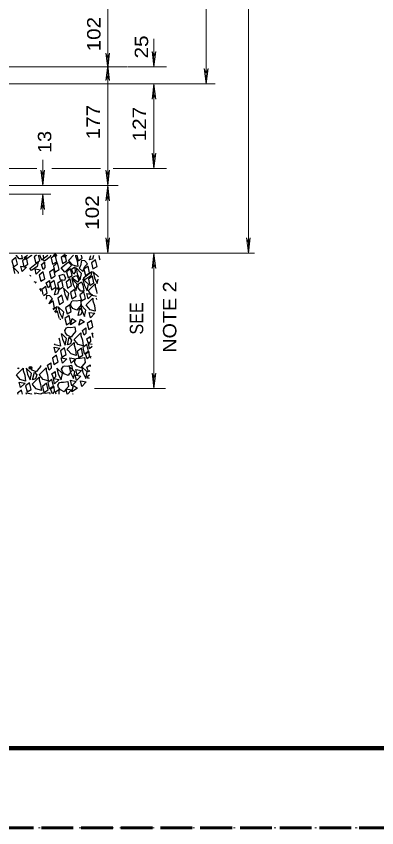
# Model space of a CAD drawing. Extents: x 312583 to 312854, y 144419 to 144597.
# Drawn here: x 312670.78 to 312691.2, y 144418.58 to 144464.5 of the extents above; entities that cross this region are included whole.
import ezdxf

# ---------------------------------------------------------------- set-up
doc = ezdxf.new("R2010")
doc.units = 0
doc.header["$LTSCALE"] = 0.3
doc.header["$PDMODE"] = 32
doc.header["$PDSIZE"] = 0.15
doc.linetypes.add('DOTTED', pattern=[1.5, 0.3, -1.2])
doc.linetypes.add('LONG_DASHED', pattern=[7.5, 6, -1.5])
for name, color, linetype, lineweight in [('1', 7, 'Continuous', 25), ('2', 7, 'Continuous', 13), ('63', 7, 'DOTTED', 13)]:
    doc.layers.add(name, color=color, linetype=linetype, lineweight=lineweight)

msp = doc.modelspace()

# ---------------------------------------------------------------- linework, layer by layer
at = {"layer": '1'}
for p, q in [((312671.6438, 144450.9791), (312671.6361, 144450.9561)), ((312672.1191, 144450.6801), (312672.0425, 144450.9791)), ((312672.7248, 144450.9791), (312672.6941, 144450.8871)), ((312672.9931, 144450.9714), (312672.9855, 144450.9714)), ((312674.1355, 144450.9714), (312674.1355, 144450.9254)), ((312674.5111, 144450.8104), (312674.4728, 144450.9714)), ((312670.9001, 144449.9518), (312670.9078, 144449.9978)), ((312671.5441, 144449.8291), (312671.5748, 144449.8521)), ((312671.5748, 144449.8521), (312671.5825, 144449.7831)), ((312671.7818, 144449.4841), (312671.9121, 144449.4611)), ((312671.9121, 144449.4611), (312671.8431, 144449.3921)), ((312672.1575, 144448.9551), (312672.1575, 144448.9398)), ((312672.3185, 144448.7021), (312672.5331, 144448.8324)), ((312675.1245, 144448.4031), (312675.2088, 144448.1348)), ((312672.8475, 144447.9354), (312672.9548, 144448.0044)), ((312673.0161, 144447.8358), (312672.9471, 144447.7821)), ((312673.1925, 144447.4294), (312673.2078, 144447.4371)), ((312673.6218, 144446.2641), (312673.3381, 144446.5478)), ((312674.9635, 144444.7844), (312674.9635, 144444.6848)), ((312673.1925, 144443.3814), (312673.2001, 144443.1208)), ((312673.9131, 144443.3584), (312673.6755, 144443.1208)), ((312671.6668, 144443.1361), (312671.6438, 144443.1208)), ((312672.1575, 144443.1361), (312672.1421, 144443.1208)), ((312673.9591, 144443.1208), (312673.9898, 144443.1361)), ((312673.9898, 144443.1361), (312673.9898, 144443.1208))]:
    msp.add_line(p, q, dxfattribs=at)
at = {"layer": '1', "lineweight": 158}
msp.add_line((312616.5, 144423.0846), (312849, 144423.0846), dxfattribs=at)
at = {"layer": '1', "linetype": 'LONG_DASHED', "lineweight": 60}
msp.add_line((312851.75, 144418.5846), (312583.526, 144418.5846), dxfattribs=at)
at = {"layer": '1'}
for points in [[(312670.8465, 144450.4654), (312670.7621, 144450.8411), (312670.5321, 144450.6648), (312670.6165, 144450.3198)], [(312671.4445, 144450.4654), (312671.3601, 144450.8411), (312671.1301, 144450.6648), (312671.2145, 144450.3198)], [(312671.9581, 144450.3428), (312671.6361, 144450.1128), (312671.5518, 144450.2278), (312672.0271, 144450.5958)], [(312672.3875, 144450.5804), (312672.4028, 144450.2738), (312672.3031, 144450.1741), (312672.2035, 144450.4501)], [(312673.0698, 144450.6111), (312672.9778, 144450.9944), (312672.7478, 144450.8181), (312672.8321, 144450.4654)], [(312673.6295, 144450.6494), (312673.5451, 144451.0251), (312673.3151, 144450.8488), (312673.3995, 144450.5038)], [(312673.7445, 144450.5958), (312673.9131, 144450.3888), (312673.5375, 144450.0131), (312673.3228, 144450.2584)], [(312674.5418, 144450.0591), (312674.6721, 144450.3351), (312674.8178, 144450.4808), (312674.6568, 144450.6648), (312674.4651, 144450.6801), (312674.4268, 144450.3734), (312674.3501, 144450.2431)], [(312675.3621, 144450.3428), (312675.2701, 144450.7184), (312675.0401, 144450.5421), (312675.1245, 144450.1971)], [(312671.3601, 144450.3044), (312671.1148, 144450.0514), (312671.0381, 144450.3581)], [(312672.1575, 144450.1434), (312671.9121, 144449.8981), (312671.8431, 144450.1971)], [(312672.9855, 144449.8061), (312672.9011, 144450.1894), (312672.6711, 144450.0131), (312672.7555, 144449.6681)], [(312673.2078, 144450.1664), (312673.1158, 144450.5421), (312672.8858, 144450.3658), (312672.9701, 144450.0208)], [(312673.9438, 144449.8368), (312673.8595, 144450.2124), (312673.6295, 144450.0438), (312673.7138, 144449.6911)], [(312674.1048, 144450.3198), (312674.1201, 144450.0131), (312674.0205, 144449.9134), (312673.9131, 144450.1894)], [(312674.4651, 144449.9518), (312674.1661, 144450.2584), (312674.2351, 144449.9211), (312674.3961, 144449.5914)], [(312674.9328, 144449.9824), (312674.8485, 144450.3581), (312674.6108, 144450.1894), (312674.7028, 144449.8368)], [(312672.4028, 144449.6451), (312672.3108, 144450.0284), (312672.0808, 144449.8521), (312672.1651, 144449.5071)], [(312673.4531, 144449.8981), (312673.5681, 144449.6911), (312673.5068, 144449.5454), (312673.2921, 144449.5914), (312673.2155, 144449.8368)], [(312674.1048, 144449.7908), (312674.1968, 144449.8214), (312674.2658, 144449.7218), (312674.3195, 144449.5454), (312674.2505, 144449.4458), (312674.1508, 144449.5224), (312674.0205, 144449.6221), (312673.9285, 144449.7064)], [(312674.9941, 144449.8061), (312674.6721, 144449.5761), (312674.5878, 144449.6911), (312675.0631, 144450.0591)], [(312675.1781, 144449.4151), (312675.0938, 144449.7908), (312674.8638, 144449.6221), (312674.9481, 144449.2694)], [(312672.6635, 144449.5454), (312672.6788, 144449.2388), (312672.5791, 144449.1391), (312672.4795, 144449.4151)], [(312673.0161, 144449.1698), (312672.9241, 144449.5454), (312672.6941, 144449.3768), (312672.7785, 144449.0241)], [(312673.4378, 144449.1851), (312673.3535, 144449.5608), (312673.1158, 144449.3844), (312673.2078, 144449.0394)], [(312673.9131, 144449.2541), (312673.8288, 144449.6374), (312673.5988, 144449.4611), (312673.6831, 144449.1084)], [(312674.2351, 144449.3461), (312673.9285, 144449.6451), (312674.0051, 144449.3154), (312674.1661, 144448.9781)], [(312674.4805, 144449.4764), (312674.5571, 144449.2848), (312674.5878, 144449.0854), (312674.6108, 144448.9398), (312674.4421, 144448.9398), (312674.2811, 144449.1238), (312674.3118, 144449.3614)], [(312674.8638, 144449.3308), (312674.5571, 144449.6298), (312674.6261, 144449.3001), (312674.7871, 144448.9628)], [(312673.1848, 144448.9934), (312673.1158, 144448.7788), (312672.9548, 144448.7328), (312673.0621, 144449.1544)], [(312673.7598, 144448.8018), (312673.4531, 144449.1084), (312673.5221, 144448.7788), (312673.6831, 144448.4414)], [(312674.1661, 144448.6638), (312674.0741, 144449.0394), (312673.8441, 144448.8631), (312673.9285, 144448.5181)], [(312674.7028, 144448.5334), (312674.6108, 144448.9091), (312674.3808, 144448.7328), (312674.4651, 144448.3878)], [(312675.0938, 144448.7481), (312674.8485, 144448.5028), (312674.7795, 144448.8018)], [(312673.4608, 144448.3341), (312673.3688, 144448.7174), (312673.1388, 144448.5411), (312673.2231, 144448.1961)], [(312674.2811, 144447.9661), (312674.2045, 144447.8588), (312673.9898, 144447.9661), (312673.8901, 144448.0964), (312673.8441, 144448.2268), (312673.9438, 144448.3878), (312674.0358, 144448.4108), (312674.1661, 144448.4031), (312674.4115, 144448.4414), (312674.4575, 144448.1654)], [(312673.4685, 144447.7591), (312673.1618, 144448.0658), (312673.2308, 144447.7284), (312673.3918, 144447.3988)], [(312673.8978, 144447.7974), (312673.8058, 144448.1731), (312673.5758, 144448.0044), (312673.6601, 144447.6518)], [(312674.5111, 144447.8204), (312674.4421, 144447.5981), (312674.2811, 144447.5598), (312674.3808, 144447.9738)], [(312674.7181, 144447.8741), (312674.4115, 144448.1808), (312674.4881, 144447.8434), (312674.6415, 144447.5138)], [(312673.8595, 144447.1918), (312673.7675, 144447.5674), (312673.5375, 144447.3988), (312673.6218, 144447.0461)], [(312674.1815, 144447.2531), (312673.8595, 144447.0461), (312673.9438, 144447.3988)], [(312674.6491, 144447.2148), (312674.3271, 144447.0154), (312674.4191, 144447.3604)], [(312675.2241, 144447.6901), (312674.9788, 144447.4371), (312674.9021, 144447.7438)], [(312673.9591, 144446.4481), (312673.8901, 144446.3484), (312673.6678, 144446.4481), (312673.5681, 144446.5784), (312673.5221, 144446.7088), (312673.6295, 144446.8698), (312673.7138, 144446.9004), (312673.8441, 144446.8851), (312674.0895, 144446.9311), (312674.1355, 144446.6551)], [(312675.1245, 144446.9158), (312675.0325, 144447.2914), (312674.8025, 144447.1228), (312674.8868, 144446.7701)], [(312674.4421, 144446.4404), (312674.5265, 144446.1721), (312674.5725, 144445.8424), (312674.2811, 144445.9268), (312674.0895, 144446.1491), (312674.0588, 144446.2028), (312674.4421, 144446.5861)], [(312674.7181, 144446.8621), (312674.7258, 144446.5554), (312674.6261, 144446.4558), (312674.5265, 144446.7241)], [(312674.0511, 144445.8961), (312674.1355, 144445.6354), (312674.1815, 144445.3058), (312673.8901, 144445.3901), (312673.6985, 144445.6124), (312673.6678, 144445.6661), (312674.0511, 144446.0418)], [(312673.9131, 144446.1798), (312673.8441, 144445.9574), (312673.6831, 144445.9114), (312673.7828, 144446.3331)], [(312674.9635, 144446.3791), (312674.9788, 144446.0724), (312674.8791, 144445.9728), (312674.7718, 144446.2488)], [(312673.2461, 144445.7121), (312673.0008, 144445.4591), (312672.9318, 144445.7658)], [(312673.5988, 144445.3594), (312673.5068, 144445.7428), (312673.2768, 144445.5664), (312673.3611, 144445.2138)], [(312674.5571, 144445.3288), (312674.4651, 144445.7121), (312674.2351, 144445.5358), (312674.3195, 144445.1908)], [(312674.8638, 144445.5511), (312674.7718, 144445.9268), (312674.5418, 144445.7581), (312674.6261, 144445.4054)], [(312673.1465, 144444.9378), (312673.0621, 144445.3211), (312672.8245, 144445.1448), (312672.9165, 144444.7921)], [(312673.6371, 144445.1141), (312673.3918, 144444.8688), (312673.3228, 144445.1754)], [(312674.1355, 144445.1141), (312673.8901, 144444.8688), (312673.8135, 144445.1678)], [(312674.5111, 144444.7078), (312674.4421, 144444.6081), (312674.2198, 144444.7078), (312674.1201, 144444.8381), (312674.0741, 144444.9684), (312674.1815, 144445.1294), (312674.2658, 144445.1601), (312674.3961, 144445.1448), (312674.6415, 144445.1908), (312674.6875, 144444.9148)], [(312674.8868, 144445.5204), (312674.9021, 144445.2138), (312674.8025, 144445.1141), (312674.7028, 144445.3901)], [(312672.4641, 144444.4624), (312672.5485, 144444.2018), (312672.5945, 144443.8644), (312672.3031, 144443.9488), (312672.1115, 144444.1711), (312672.0885, 144444.2324), (312672.4641, 144444.6081)], [(312672.7401, 144444.8841), (312672.7555, 144444.5774), (312672.6481, 144444.4778), (312672.5485, 144444.7538)], [(312673.7828, 144444.2708), (312673.7138, 144444.1711), (312673.4915, 144444.2708), (312673.3918, 144444.4011), (312673.3458, 144444.5314), (312673.4531, 144444.6924), (312673.5375, 144444.7231), (312673.6678, 144444.7078), (312673.9131, 144444.7538), (312673.9591, 144444.4778)], [(312674.0895, 144444.3704), (312673.7828, 144444.6771), (312673.8595, 144444.3474), (312674.0205, 144444.0101)], [(312674.7871, 144444.3704), (312674.4805, 144444.6771), (312674.5571, 144444.3474), (312674.7181, 144444.0101)], [(312671.1685, 144444.4471), (312671.2605, 144444.1864), (312671.2988, 144443.8491), (312671.0075, 144443.9411), (312670.8235, 144444.1558), (312670.7928, 144444.2171), (312671.1685, 144444.5928)], [(312671.6515, 144444.2861), (312671.3448, 144444.5928), (312671.4138, 144444.2554), (312671.5748, 144443.9258)], [(312671.9428, 144444.2018), (312671.8661, 144443.9794), (312671.7051, 144443.9334), (312671.8125, 144444.3551)], [(312672.9855, 144444.4011), (312673.0008, 144444.1021), (312672.9011, 144443.9948), (312672.7938, 144444.2708)], [(312673.3918, 144444.2861), (312673.0851, 144444.5928), (312673.1618, 144444.2554), (312673.3228, 144443.9258)], [(312674.4421, 144444.1404), (312674.1968, 144443.8951), (312674.1201, 144444.2018)], [(312674.4728, 144444.4624), (312674.2198, 144444.2094), (312674.1508, 144444.5161)], [(312671.2758, 144443.7341), (312671.0228, 144443.4888), (312670.9538, 144443.7878)], [(312671.6208, 144443.3891), (312671.5288, 144443.7648), (312671.2988, 144443.5884), (312671.3908, 144443.2434)], [(312672.0731, 144443.9258), (312672.1575, 144443.6574), (312672.2035, 144443.3278), (312671.9121, 144443.4121), (312671.7205, 144443.6344), (312671.6898, 144443.6881), (312672.0731, 144444.0714)], [(312672.5791, 144443.3584), (312672.4948, 144443.7341), (312672.2571, 144443.5578), (312672.3491, 144443.2128)], [(312672.8858, 144443.5731), (312672.7938, 144443.9488), (312672.5638, 144443.7801), (312672.6481, 144443.4274)], [(312673.2078, 144443.9488), (312672.9548, 144443.7034), (312672.8858, 144444.0101)], [(312673.5681, 144443.3584), (312673.4915, 144443.2511), (312673.2768, 144443.3584), (312673.1771, 144443.4888), (312673.1311, 144443.6191), (312673.2308, 144443.7801), (312673.3228, 144443.8031), (312673.4531, 144443.7954), (312673.6985, 144443.8338), (312673.7445, 144443.5578)], [(312674.1738, 144443.8414), (312673.9285, 144443.5961), (312673.8595, 144443.9028)], [(312674.7411, 144443.8108), (312674.4881, 144443.5578), (312674.4191, 144443.8644)], [(312672.9165, 144443.5424), (312672.9241, 144443.2434), (312672.8245, 144443.1361), (312672.7248, 144443.4121)], [(312674.2505, 144443.4581), (312673.9285, 144443.2511), (312674.0205, 144443.6038)]]:
    msp.add_lwpolyline(points, close=True, dxfattribs=at)
for points in [[(312671.0841, 144450.9868), (312671.0995, 144450.9101), (312671.1225, 144450.7644), (312670.9538, 144450.7644), (312670.7928, 144450.9561), (312670.7928, 144450.9868)], [(312671.6361, 144450.9561), (312671.3141, 144450.7261), (312671.2298, 144450.8411), (312671.4138, 144450.9791)], [(312671.9198, 144450.9791), (312671.7971, 144450.8871), (312671.8815, 144450.5344), (312672.1191, 144450.6801)], [(312672.3108, 144450.9791), (312672.3185, 144450.7951), (312672.2188, 144450.6954), (312672.1115, 144450.9714), (312672.1268, 144450.9791)], [(312672.6941, 144450.8871), (312672.3798, 144450.6494), (312672.2878, 144450.7721), (312672.5638, 144450.9791)], [(312673.6141, 144450.9714), (312673.6141, 144450.9561), (312673.5145, 144450.8564), (312673.4685, 144450.9714)], [(312674.1355, 144450.9254), (312674.2198, 144450.6648), (312674.2658, 144450.3351), (312673.9745, 144450.4194), (312673.7828, 144450.6418), (312673.7521, 144450.6954), (312674.0281, 144450.9714)], [(312674.2045, 144450.9714), (312674.2811, 144450.6648), (312674.5111, 144450.8104)], [(312675.1628, 144450.9638), (312675.0938, 144450.7568), (312674.9328, 144450.7108), (312674.9941, 144450.9638)], [(312675.4541, 144450.9638), (312675.5001, 144450.7491), (312675.5155, 144450.7184)], [(312670.9078, 144449.9978), (312670.6011, 144450.3044), (312670.6778, 144449.9671), (312670.6855, 144449.9518)], [(312675.4311, 144449.7448), (312675.1398, 144450.0438), (312675.2088, 144449.7064), (312675.3698, 144449.3768), (312675.4158, 144449.6221)], [(312672.5331, 144448.8324), (312672.4488, 144449.2158), (312672.2188, 144449.0394), (312672.2878, 144448.7481)], [(312675.3238, 144448.6331), (312675.0785, 144448.7021), (312674.8868, 144448.9244), (312674.8638, 144448.9781), (312675.2395, 144449.3614), (312675.2395, 144449.2158)], [(312675.2395, 144449.2158), (312675.3238, 144448.9551), (312675.3468, 144448.8094)], [(312672.0961, 144449.0318), (312672.1575, 144449.1008), (312672.1575, 144448.9551)], [(312672.6405, 144448.2344), (312672.6941, 144448.3571), (312672.8398, 144448.5028), (312672.6788, 144448.6868), (312672.4948, 144448.7021), (312672.4641, 144448.4951)], [(312672.9548, 144448.0044), (312672.8705, 144448.3878), (312672.6481, 144448.2191)], [(312675.2548, 144447.8051), (312675.2548, 144447.8051), (312674.9635, 144447.8894), (312674.7718, 144448.1118), (312674.7411, 144448.1654), (312675.1245, 144448.5488), (312675.1245, 144448.4031)], [(312675.3161, 144448.5258), (312675.3008, 144448.5411), (312675.3161, 144448.4721)], [(312672.8628, 144447.9124), (312673.0851, 144448.0811), (312673.0161, 144447.8358)], [(312673.2078, 144447.4371), (312673.1158, 144447.8204), (312672.9931, 144447.7208)], [(312675.2088, 144448.1348), (312675.2548, 144447.8051), (312675.2548, 144447.8051)], [(312673.2385, 144447.3604), (312673.2615, 144447.3834), (312673.2615, 144447.3298)], [(312673.3305, 144446.5324), (312673.3918, 144446.2334), (312673.5528, 144445.8961), (312673.6218, 144446.2641)], [(312675.1321, 144446.5018), (312675.0631, 144446.5708), (312675.1168, 144446.3254)], [(312673.1848, 144446.3101), (312673.2308, 144446.1644), (312673.2768, 144445.8271), (312672.9855, 144445.9114), (312672.9471, 144445.9574)], [(312675.0708, 144445.8194), (312674.9328, 144445.6814), (312674.8638, 144445.9881), (312675.0785, 144445.9421)], [(312675.0095, 144445.1448), (312674.9788, 144445.2291), (312675.0171, 144445.2598)], [(312671.9811, 144444.4778), (312671.9121, 144444.3704), (312671.6898, 144444.4778), (312671.5901, 144444.6081)], [(312672.1498, 144444.7384), (312672.1575, 144444.6771), (312671.9811, 144444.4778)], [(312674.9481, 144444.4394), (312674.8791, 144444.3704), (312674.7718, 144444.6464), (312674.9635, 144444.7844)], [(312670.9538, 144444.6004), (312670.8925, 144444.5468), (312670.8848, 144444.6004)], [(312674.9021, 144444.0178), (312674.8715, 144443.9948), (312674.7871, 144444.1098), (312674.9251, 144444.2171)], [(312671.1378, 144443.1208), (312671.0841, 144443.3431), (312670.8465, 144443.1668), (312670.8618, 144443.1208)], [(312673.0468, 144443.1208), (312673.0008, 144443.2511), (312673.1925, 144443.3814)], [(312673.6678, 144443.1208), (312673.5988, 144443.4121), (312673.9131, 144443.3584)], [(312671.3601, 144443.1208), (312671.3448, 144443.1974), (312671.6668, 144443.1361)], [(312671.8585, 144443.1208), (312671.8355, 144443.1974), (312672.1575, 144443.1361)], [(312672.1805, 144443.1208), (312672.2035, 144443.1514), (312672.2878, 144443.1821), (312672.4181, 144443.1668), (312672.6635, 144443.2128), (312672.6788, 144443.1208)]]:
    msp.add_lwpolyline(points, dxfattribs=at)
for p in [(312672.9855, 144450.9714), (312671.5901, 144444.6081)]:
    msp.add_point(p, dxfattribs=at)
at = {"layer": '2'}
for p, q in [((312681.5338, 144460.6698), (312681.5338, 144494.2114)), ((312683.9258, 144451.0864), (312683.9258, 144494.2114)), ((312675.9601, 144465.4614), (312675.9601, 144461.7431)), ((312678.5745, 144461.6281), (312678.5745, 144463.2228)), ((312675.8528, 144462.4024), (312675.9601, 144462.1264)), ((312675.9601, 144461.5361), (312675.8528, 144462.4024)), ((312676.0675, 144462.4024), (312675.9601, 144462.1264)), ((312675.9601, 144461.5361), (312676.0675, 144462.4024)), ((312678.4671, 144462.4944), (312678.5745, 144462.2184)), ((312678.5745, 144461.6281), (312678.4671, 144462.4944)), ((312678.6818, 144462.4944), (312678.5745, 144462.2184)), ((312678.5745, 144461.6281), (312678.6818, 144462.4944)), ((312665.5258, 144461.6281), (312677.0488, 144461.6281)), ((312675.9601, 144461.7278), (312675.8528, 144460.8614)), ((312675.9601, 144461.7278), (312676.0675, 144460.8614)), ((312677.0718, 144461.6281), (312679.2951, 144461.6281)), ((312675.8528, 144460.8614), (312675.9601, 144461.1374)), ((312676.0675, 144460.8614), (312675.9601, 144461.1374)), ((312681.4265, 144461.5361), (312681.5338, 144461.2601)), ((312681.5338, 144460.6698), (312681.4265, 144461.5361)), ((312681.6411, 144461.5361), (312681.5338, 144461.2601)), ((312681.5338, 144460.6698), (312681.6411, 144461.5361)), ((312667.2355, 144460.6698), (312682.0475, 144460.6698)), ((312678.5745, 144460.6698), (312678.4671, 144459.8034)), ((312678.5745, 144455.8781), (312678.5745, 144460.6698)), ((312678.5745, 144460.6698), (312678.6818, 144459.8034)), ((312678.4671, 144459.8034), (312678.5745, 144460.0794)), ((312678.6818, 144459.8034), (312678.5745, 144460.0794)), ((312678.4671, 144456.7444), (312678.5745, 144456.4684)), ((312678.5745, 144455.8781), (312678.4671, 144456.7444)), ((312678.6818, 144456.7444), (312678.5745, 144456.4684)), ((312678.5745, 144455.8781), (312678.6818, 144456.7444)), ((312672.2801, 144454.9198), (312672.2801, 144456.3688)), ((312667.2585, 144455.8781), (312671.9428, 144455.8781)), ((312672.1728, 144455.7861), (312672.2801, 144455.5101)), ((312672.2801, 144454.9198), (312672.1728, 144455.7861)), ((312672.3875, 144455.7861), (312672.2801, 144455.5101)), ((312672.2801, 144454.9198), (312672.3875, 144455.7861)), ((312672.7938, 144455.8781), (312675.5538, 144455.8781)), ((312675.8528, 144455.7861), (312675.9601, 144455.5101)), ((312675.9601, 144454.9198), (312675.8528, 144455.7861)), ((312676.0675, 144455.7861), (312675.9601, 144455.5101)), ((312675.9601, 144454.9198), (312676.0675, 144455.7861)), ((312676.2745, 144455.8781), (312679.2951, 144455.8781)), ((312664.0231, 144454.9198), (312676.5581, 144454.9198)), ((312675.9601, 144454.9198), (312675.8528, 144454.0534)), ((312675.9601, 144454.9198), (312676.0675, 144454.0534)), ((312658.3958, 144454.4368), (312672.7401, 144454.4368)), ((312672.2801, 144454.4368), (312672.1728, 144453.5704)), ((312672.2801, 144453.2561), (312672.2801, 144454.4368)), ((312672.2801, 144454.4368), (312672.3875, 144453.5704)), ((312675.8528, 144454.0534), (312675.9601, 144454.3294)), ((312676.0675, 144454.0534), (312675.9601, 144454.3294)), ((312672.1728, 144453.5704), (312672.2801, 144453.8464)), ((312672.3875, 144453.5704), (312672.2801, 144453.8464)), ((312675.8528, 144451.9528), (312675.9601, 144451.6768)), ((312675.9601, 144451.0864), (312675.8528, 144451.9528)), ((312676.0675, 144451.9528), (312675.9601, 144451.6768)), ((312675.9601, 144451.0864), (312676.0675, 144451.9528)), ((312683.8185, 144451.9528), (312683.9258, 144451.6768)), ((312683.9258, 144451.0864), (312683.8185, 144451.9528)), ((312684.0331, 144451.9528), (312683.9258, 144451.6768)), ((312683.9258, 144451.0864), (312684.0331, 144451.9528)), ((312670.2331, 144451.0864), (312684.2708, 144451.0864)), ((312678.5745, 144451.0864), (312678.4671, 144450.2201)), ((312678.5745, 144451.0864), (312678.5745, 144443.4351)), ((312678.5745, 144451.0864), (312678.6818, 144450.2201)), ((312678.4671, 144450.2201), (312678.5745, 144450.4961)), ((312678.6818, 144450.2201), (312678.5745, 144450.4961)), ((312678.4671, 144444.3014), (312678.5745, 144444.0254)), ((312678.5745, 144443.4351), (312678.4671, 144444.3014)), ((312678.6818, 144444.3014), (312678.5745, 144444.0254)), ((312678.5745, 144443.4351), (312678.6818, 144444.3014)), ((312675.2165, 144443.4351), (312679.2261, 144443.4351))]:
    msp.add_line(p, q, dxfattribs=at)
msp.add_lwpolyline([(312675.9601, 144451.0864), (312675.9601, 144454.9198), (312675.9601, 144461.6588)], dxfattribs=at)
at = {"layer": '63'}
msp.add_lwpolyline([(312601.2, 144418.5846), (312853.5, 144418.5846), (312853.5, 144596.7846)], dxfattribs=at)

# ---------------------------------------------------------------- texts
at = {"layer": '2'}
for s, width, p in [('102 ', 1.15, (312675.5515, 144462.5086)), ('25 ', 1.15, (312678.248, 144462.1101)), ('177 ', 1.15, (312675.516, 144457.5321)), ('127 ', 1.15, (312678.1304, 144457.421)), ('13 ', 1.1, (312672.7643, 144456.7645)), ('102 ', 1.15, (312675.4593, 144452.4134)), ('NOTE 2', 1.1, (312679.8471, 144445.4587)), ('SEE', 0.9, (312677.9704, 144446.4855))]:
    msp.add_text(s, height=0.76, rotation=90, dxfattribs=dict(at, width=width)).set_placement(p)

doc.saveas('drawing.dxf')
